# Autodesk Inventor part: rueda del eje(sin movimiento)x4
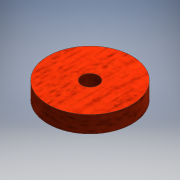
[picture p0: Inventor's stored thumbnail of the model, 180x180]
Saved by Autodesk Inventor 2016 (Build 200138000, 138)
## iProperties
Created: 2016-06
Part Number: rueda del eje(sin movimiento)x4
Material: Genérico
Document SubType Name: Modeling
Designer: adm
Density: 1 g/cm^3
Appearance: Valor por defecto
Author: adm
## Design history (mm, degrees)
sketch "Boceto1"
  geometry: C1 r 25 at (0, 0); 1 further point
  constraints: 1 centre point, 1 coincident
  dimensions: "d0" = 50 diameter of C1
extrude "Extrusión1" new body sketch "Boceto1" distance "d1" = 10; taper "d2" = 0 deg
sketch "Boceto2"
  geometry: C1 r 5 at (0, 0); 1 further point
  constraints: 1 centre point, 1 coincident
  dimensions: "d3" = 10 diameter of C1
extrude "Extrusión2" cut sketch "Boceto2" distance "d4" = 10; taper "d5" = 0 deg
node "Sólido1"
